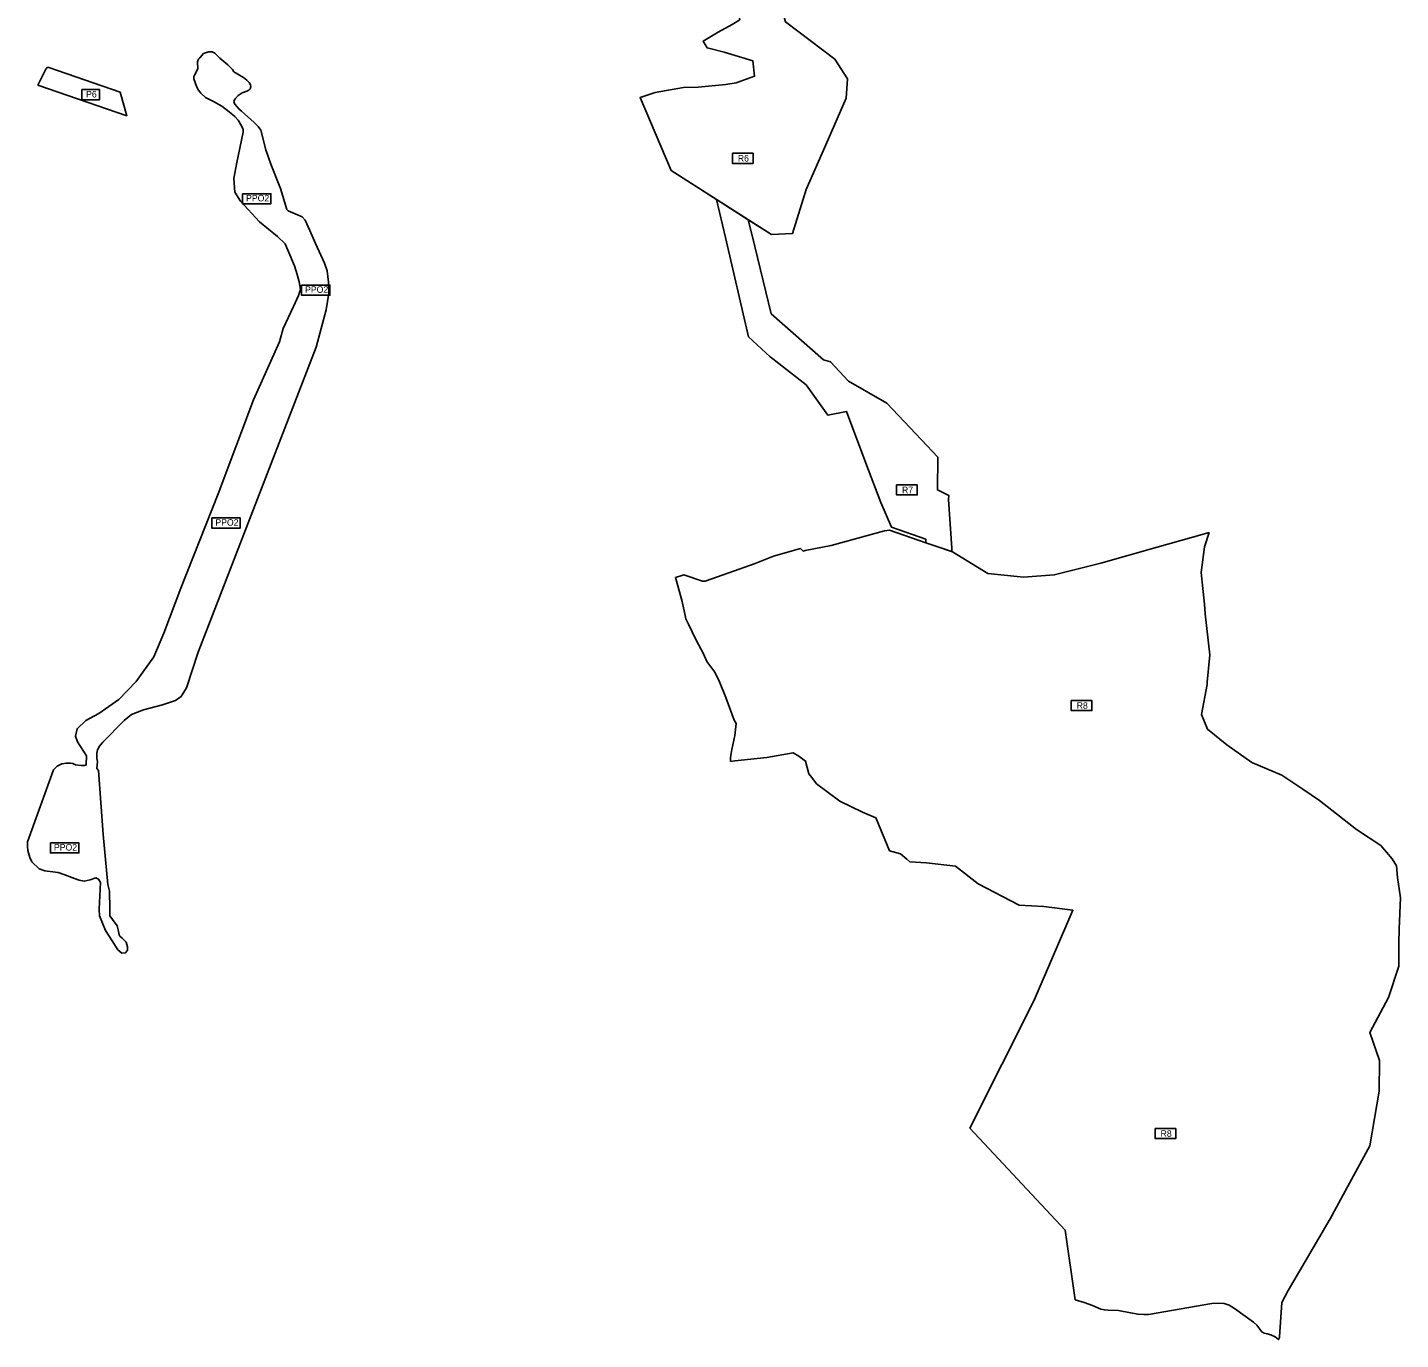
# Model space of a CAD drawing. Extents: x -545342 to -528609, y -1041871 to -1035695.
# Drawn here: x -542551 to -540434, y -1041871 to -1039848 of the extents above; entities that cross this region are included whole.
import ezdxf

# ---------------------------------------------------------------- set-up
doc = ezdxf.new("R2010")
doc.units = 0
for name, color, linetype in [('Vrstva 30', 7, 'Continuous'), ('Vrstva 31', 7, 'Continuous'), ('Vrstva 32', 7, 'Continuous'), ('Vrstva 44', 7, 'Continuous'), ('Vrstva 5', 7, 'Continuous'), ('Vrstva 6', 7, 'Continuous'), ('Vrstva 61', 7, 'Continuous'), ('Vrstva 7', 7, 'Continuous'), ('Vrstva66', 7, 'Continuous')]:
    doc.layers.add(name, color=color, linetype=linetype)

msp = doc.modelspace()

# ---------------------------------------------------------------- linework, layer by layer
at = {"layer": 'Vrstva 30'}
msp.add_lwpolyline([(-540634.1, -1041863.7), (-540627.2, -1041866.5), (-540622.1, -1041870.9), (-540620.8, -1041867.7), (-540620.7, -1041866.5), (-540617.2, -1041813.7), (-540607.4, -1041795), (-540542.4, -1041684.7), (-540512.7, -1041629.5), (-540481.6, -1041572), (-540466.9, -1041488.1), (-540466.7, -1041440.7), (-540481.4, -1041397.5), (-540452.8, -1041343.7), (-540436.6, -1041295), (-540436.6, -1041255.9), (-540436.2, -1041241), (-540436.2, -1041237.7), (-540434.1, -1041189.6), (-540438.6, -1041158.6), (-540440.3, -1041140.5), (-540446.9, -1041129.5), (-540464.2, -1041109.2), (-540501.8, -1041084.2), (-540558.9, -1041039.9), (-540584.7, -1041022.3), (-540617.3, -1041000.7), (-540663.1, -1040981.3), (-540701.9, -1040954.1), (-540731.5, -1040929.6), (-540740.7, -1040906.9), (-540732.4, -1040860.8), (-540732, -1040857.1), (-540728.2, -1040815.2), (-540735.1, -1040752.1), (-540736.5, -1040737.2), (-540738.7, -1040712.9), (-540741.2, -1040688.2), (-540736.1, -1040648.6), (-540729.2, -1040626.7), (-540756.3, -1040634.3), (-540809, -1040649), (-540896, -1040674), (-540968, -1040692), (-541015.2, -1040695.2), (-541025.2, -1040694.1), (-541070.4, -1040689.6), (-541125, -1040656.3), (-541152, -1040647), (-541166, -1040642.2), (-541222, -1040623), (-541229.8, -1040623.8), (-541312, -1040646.4), (-541352.1, -1040654.3), (-541355.1, -1040655.1), (-541357, -1040653.3), (-541359.2, -1040651.3), (-541400.9, -1040663.2), (-541428.9, -1040674.3), (-541460.7, -1040685.5), (-541506, -1040701.4), (-541510.3, -1040701.4), (-541539, -1040692), (-541541.8, -1040692.8), (-541551.9, -1040695.7), (-541550.8, -1040699.6), (-541541.4, -1040733.1), (-541536.3, -1040757), (-541535.7, -1040759.7), (-541531.8, -1040767.9), (-541520.5, -1040791.5), (-541508.8, -1040813.8), (-541503.5, -1040825.3), (-541491.3, -1040841.6), (-541484.1, -1040856.7), (-541474.3, -1040881.1), (-541461.4, -1040915.8), (-541458.3, -1040921.1), (-541460.1, -1040939.4), (-541464.7, -1040961.2), (-541467.2, -1040973.5), (-541466.9, -1040979.4), (-541460.4, -1040978.7), (-541410.9, -1040973.2), (-541370.6, -1040966), (-541361.4, -1040971.4), (-541351.5, -1040979), (-541346.1, -1040998.5), (-541341.8, -1041004.2), (-541334.5, -1041013.9), (-541298.2, -1041041), (-541263.5, -1041057.7), (-541242.7, -1041066.5), (-541242.4, -1041067.3), (-541221.8, -1041117.1), (-541205, -1041121.8), (-541195.2, -1041130), (-541190.3, -1041134.1), (-541165, -1041136), (-541120, -1041141), (-541085, -1041168), (-541022, -1041201), (-540984, -1041203), (-540939, -1041209), (-540998.8, -1041347.7), (-541098, -1041545), (-540951, -1041702), (-540935.4, -1041809.6), (-540921.7, -1041813.6), (-540908.7, -1041818.2), (-540896.1, -1041823.8), (-540890.6, -1041825.1), (-540885, -1041825.8), (-540868.7, -1041826.3), (-540850.1, -1041829.5), (-540838.7, -1041831.8), (-540829.9, -1041832.5), (-540822.6, -1041832), (-540724.9, -1041815.4), (-540715, -1041814.9), (-540706.1, -1041815.4), (-540698.1, -1041817.9), (-540689.8, -1041823), (-540660.5, -1041843.9), (-540655.6, -1041848.6), (-540647.9, -1041859.1), (-540644.4, -1041861.2), (-540639.6, -1041862.3), (-540634.1, -1041863.7)], dxfattribs=at)
at = {"layer": 'Vrstva 31'}
msp.add_lwpolyline([(-541165.9, -1040636.8), (-541218.6, -1040618.3), (-541235.1, -1040580.1), (-541258.1, -1040519.5), (-541288.2, -1040439.9), (-541316.9, -1040445.7), (-541350.1, -1040399), (-541401.9, -1040358.6), (-541405.8, -1040355.7), (-541439.2, -1040324.8), (-541474.8, -1040171.6), (-541488.5, -1040112.9), (-541439.6, -1040144.2), (-541433.7, -1040168.3), (-541404.5, -1040289.1), (-541323.6, -1040360), (-541312.7, -1040363.1), (-541285.3, -1040393), (-541225.8, -1040427.1), (-541172.5, -1040483.8), (-541147.5, -1040510.4), (-541148, -1040560.7), (-541130.4, -1040569.3), (-541131, -1040575.4), (-541125.9, -1040650.7), (-541125.7, -1040656), (-541152, -1040647), (-541165.7, -1040642.3), (-541165.9, -1040636.8)], dxfattribs=at)
at = {"layer": 'Vrstva 32'}
for points in [[(-541306.1, -1039896.5), (-541382.4, -1039839.1), (-541393.7, -1039799.2), (-541405.3, -1039790.4), (-541448.3, -1039803.6), (-541454.8, -1039808.4), (-541460.3, -1039818.1), (-541454.1, -1039827.2), (-541452.7, -1039835.8), (-541464.4, -1039843.4), (-541485.8, -1039854.9), (-541509, -1039868.7), (-541503, -1039879.2), (-541476.8, -1039885.6), (-541432.3, -1039899.4)], [(-541432.3, -1039899.4), (-541429.9, -1039923.1)], [(-541403.8, -1040167), (-541371.5, -1040165.6), (-541350.4, -1040097.4), (-541319.8, -1040028.8), (-541288.9, -1039956.9), (-541286.8, -1039926.8), (-541306.1, -1039896.5)], [(-541429.9, -1039923.1), (-541458.2, -1039933.1), (-541474.1, -1039935.7), (-541517, -1039939.8), (-541539.3, -1039940.2), (-541583.1, -1039948.1), (-541606.4, -1039955.7), (-541558.2, -1040068.4), (-541403.8, -1040167)]]:
    msp.add_lwpolyline(points, dxfattribs=at)
at = {"layer": 'Vrstva 44'}
msp.add_lwpolyline([(-542520.1, -1039908.8), (-542522.2, -1039912.1), (-542534.6, -1039936.6), (-542397.8, -1039983.8), (-542408.1, -1039947.7), (-542517.8, -1039909.6), (-542520.1, -1039908.8)], dxfattribs=at)
at = {"layer": 'Vrstva 5'}
for points in [[(-541210.9, -1040553.1), (-541179.2, -1040553.1), (-541179.2, -1040568.6), (-541210.9, -1040568.6)], [(-540941.6, -1040885.6), (-540909.9, -1040885.6), (-540909.9, -1040901.1), (-540941.6, -1040901.1)], [(-540812.3, -1041545.6), (-540780.6, -1041545.6), (-540780.6, -1041561.1), (-540812.3, -1041561.1)]]:
    msp.add_lwpolyline(points, close=True, dxfattribs=at)
at = {"layer": 'Vrstva 6'}
msp.add_lwpolyline([(-541463.9, -1040041.7), (-541432.2, -1040041.7), (-541432.2, -1040057.3), (-541463.9, -1040057.3)], close=True, dxfattribs=at)
at = {"layer": 'Vrstva 61'}
msp.add_lwpolyline([(-542285.2, -1039894.7), (-542279.3, -1039888), (-542271.9, -1039885.1), (-542266, -1039885.4), (-542262.1, -1039887.2), (-542254.3, -1039894.9), (-542241.7, -1039905.2), (-542234.8, -1039912.7), (-542232.7, -1039916.1), (-542217.8, -1039925.1), (-542212.4, -1039929.2), (-542209, -1039932.5), (-542206.8, -1039936.2), (-542206.6, -1039939), (-542207.6, -1039942.3), (-542209.5, -1039944.5), (-542212.4, -1039946.2), (-542219.9, -1039948.5), (-542225.7, -1039952.5), (-542230.6, -1039957.8), (-542232.1, -1039960.4), (-542232.4, -1039962), (-542232.2, -1039963.4), (-542231.3, -1039966), (-542227.6, -1039970.2), (-542225.1, -1039973.3), (-542221, -1039976.6), (-542216, -1039981), (-542201.1, -1039994.1), (-542195, -1040000.4), (-542190.8, -1040006), (-542183.1, -1040036.5), (-542175.4, -1040058.8), (-542160.9, -1040096), (-542150.8, -1040128.3), (-542148.9, -1040130.6), (-542145.3, -1040132.3), (-542127.5, -1040139.7), (-542122.9, -1040144.9), (-542115.4, -1040160.7), (-542106.6, -1040180.8), (-542092.6, -1040211.4), (-542088.9, -1040223), (-542086.7, -1040240.6), (-542086.2, -1040257.3), (-542090.4, -1040283), (-542105.9, -1040340.8), (-542265.4, -1040753.7), (-542287.4, -1040810.8), (-542305.6, -1040866.1), (-542314, -1040879.6), (-542322.8, -1040885.7), (-542342.8, -1040892.2), (-542371.9, -1040900.1), (-542390.3, -1040907.3), (-542401.8, -1040916.4), (-542434.5, -1040949.7), (-542439.5, -1040955.9), (-542443, -1040961.5), (-542443.8, -1040966.8), (-542443.9, -1040970.1), (-542443.6, -1040974.8), (-542443, -1040979.8), (-542443.7, -1040990.3), (-542441.5, -1040993.5), (-542433.9, -1041092.2), (-542426.9, -1041169.3), (-542424.5, -1041179.5), (-542424, -1041206.9), (-542423.6, -1041217.3), (-542419.6, -1041223.2), (-542412.4, -1041232.8), (-542410.7, -1041239.1), (-542409.5, -1041246.9), (-542408.6, -1041248.9), (-542404.9, -1041251.8), (-542398.8, -1041257.9), (-542396.6, -1041265.1), (-542396.4, -1041270.4), (-542399.6, -1041274.4), (-542405.1, -1041275.2), (-542411.5, -1041269.9), (-542420.3, -1041256.3), (-542430.6, -1041240.1), (-542439.5, -1041217.7), (-542440.3, -1041207.4), (-542438.1, -1041166.4), (-542441, -1041161.1), (-542445.2, -1041158.7), (-542454, -1041161.8), (-542463.3, -1041164.2), (-542470.8, -1041162.6), (-542478.5, -1041160.2), (-542493.4, -1041154.4), (-542503.2, -1041150.9), (-542511.7, -1041149.9), (-542524.2, -1041148.3), (-542532.7, -1041145.3), (-542544.1, -1041134.4), (-542547, -1041127.5), (-542550, -1041116.9), (-542550.5, -1041110.5), (-542550.8, -1041103.6), (-542510.4, -1040992.3), (-542504.9, -1040986.7), (-542497.9, -1040983.1), (-542490.9, -1040982.2), (-542484.7, -1040981.9), (-542480.6, -1040982.9), (-542476.8, -1040984.7), (-542468.1, -1040985.8), (-542462.6, -1040985.7), (-542460.1, -1040984.9), (-542459.9, -1040970.7), (-542473.4, -1040949.2), (-542476.6, -1040940.4), (-542474.3, -1040929.2), (-542460.8, -1040916.2), (-542440.8, -1040905.5), (-542410.1, -1040884.1), (-542383.2, -1040856.1), (-542355.7, -1040818), (-542340.4, -1040781.6), (-542314.4, -1040712.3), (-542256.6, -1040567.1), (-542202.5, -1040421.7), (-542162.1, -1040332.6), (-542156.5, -1040311.7), (-542140.4, -1040277.8), (-542132.7, -1040260.8), (-542130.1, -1040251.7), (-542131.7, -1040239.9), (-542135.2, -1040228.7), (-542139.3, -1040215.5), (-542149.2, -1040191), (-542153.7, -1040181.4), (-542165.4, -1040170.2), (-542193.3, -1040147.4), (-542222.6, -1040115.7), (-542231.1, -1040101.8), (-542232.7, -1040080.6), (-542227.8, -1040056.2), (-542218, -1040009.3), (-542218.1, -1040005.3), (-542220.7, -1039999.3), (-542226, -1039990.7), (-542231, -1039984.9), (-542239.6, -1039977.6), (-542250.9, -1039969.1), (-542263.8, -1039961.8), (-542276.5, -1039955.6), (-542283.6, -1039949.1), (-542287.2, -1039944.2), (-542289.8, -1039940), (-542294.4, -1039926.8), (-542294.1, -1039923.5), (-542293.5, -1039921.2), (-542288.1, -1039911.7), (-542288.4, -1039900.6), (-542286.9, -1039896.5)], close=True, dxfattribs=at)
at = {"layer": 'Vrstva 7'}
for points in [[(-542467.1, -1039943.6), (-542439.7, -1039943.6), (-542439.7, -1039959.2), (-542467.1, -1039959.2)], [(-542219.3, -1040104.1), (-542175.4, -1040104.1), (-542175.4, -1040119.6), (-542219.3, -1040119.6)], [(-542128.2, -1040245.1), (-542084.4, -1040245.1), (-542084.4, -1040260.6), (-542128.2, -1040260.6)], [(-542266.6, -1040604.1), (-542222.7, -1040604.1), (-542222.7, -1040619.7), (-542266.6, -1040619.7)], [(-542515.3, -1041105.1), (-542471.5, -1041105.1), (-542471.5, -1041120.6), (-542515.3, -1041120.6)]]:
    msp.add_lwpolyline(points, close=True, dxfattribs=at)
at = {"layer": 'Vrstva66'}
for points in [[(-541464.4, -1039843.4), (-541485.8, -1039854.9), (-541509, -1039868.7), (-541503, -1039879.2), (-541476.8, -1039885.6), (-541432.3, -1039899.4), (-541429.9, -1039923.1), (-541458.2, -1039933.1), (-541474.1, -1039935.7), (-541517, -1039939.8), (-541539.3, -1039940.2), (-541583.1, -1039948.1), (-541606.4, -1039955.7), (-541558.2, -1040068.4), (-541488.5, -1040112.9), (-541439.6, -1040144.2), (-541403.8, -1040167), (-541371.5, -1040165.6), (-541350.4, -1040097.4), (-541319.8, -1040028.8), (-541288.9, -1039956.9), (-541286.8, -1039926.8), (-541306.1, -1039896.5), (-541382.4, -1039839.1)], [(-541165.7, -1040642.3), (-541152, -1040647), (-541125.7, -1040656), (-541125.9, -1040650.7), (-541131, -1040575.4), (-541130.4, -1040569.3), (-541148, -1040560.7), (-541147.5, -1040510.4), (-541172.5, -1040483.8), (-541225.8, -1040427.1), (-541285.3, -1040393), (-541312.7, -1040363.1), (-541323.6, -1040360), (-541404.5, -1040289.1), (-541433.7, -1040168.3), (-541439.6, -1040144.2), (-541488.5, -1040112.9), (-541474.8, -1040171.6), (-541439.2, -1040324.8), (-541405.8, -1040355.7), (-541401.9, -1040358.6), (-541350.1, -1040399), (-541316.9, -1040445.7), (-541288.2, -1040439.9), (-541258.1, -1040519.5), (-541235.1, -1040580.1), (-541218.6, -1040618.3), (-541165.9, -1040636.8), (-541165.7, -1040642.3)], [(-541165.7, -1040642.3), (-541166, -1040642.2), (-541222, -1040623), (-541229.8, -1040623.8), (-541312, -1040646.4), (-541352.1, -1040654.3), (-541355.1, -1040655.1), (-541357, -1040653.3), (-541359.2, -1040651.3), (-541400.9, -1040663.2), (-541428.9, -1040674.3), (-541460.7, -1040685.5), (-541506, -1040701.4), (-541510.3, -1040701.4), (-541539, -1040692), (-541541.8, -1040692.8), (-541551.9, -1040695.7), (-541550.8, -1040699.6), (-541541.4, -1040733.1), (-541536.3, -1040757), (-541535.7, -1040759.7), (-541531.8, -1040767.9), (-541520.5, -1040791.5), (-541508.8, -1040813.8), (-541503.5, -1040825.3), (-541491.3, -1040841.6), (-541484.1, -1040856.7), (-541474.3, -1040881.1), (-541461.4, -1040915.8), (-541458.3, -1040921.1), (-541460.1, -1040939.4), (-541464.7, -1040961.2), (-541467.2, -1040973.5), (-541466.9, -1040979.4), (-541460.4, -1040978.7), (-541410.9, -1040973.2), (-541370.6, -1040966), (-541361.4, -1040971.4), (-541351.5, -1040979), (-541346.1, -1040998.5), (-541341.8, -1041004.2), (-541334.5, -1041013.9), (-541298.2, -1041041), (-541263.5, -1041057.7), (-541242.7, -1041066.5), (-541242.4, -1041067.3), (-541221.8, -1041117.1), (-541205, -1041121.8), (-541195.2, -1041130), (-541190.3, -1041134.1), (-541165, -1041136), (-541120, -1041141), (-541085, -1041168), (-541022, -1041201), (-540984, -1041203), (-540939, -1041209), (-540998.8, -1041347.7), (-541098, -1041545), (-540951, -1041702), (-540935.4, -1041809.6), (-540921.7, -1041813.6), (-540908.7, -1041818.2), (-540896.1, -1041823.8), (-540890.6, -1041825.1), (-540885, -1041825.8), (-540868.7, -1041826.3), (-540850.1, -1041829.5), (-540838.7, -1041831.8), (-540829.9, -1041832.5), (-540822.6, -1041832), (-540724.9, -1041815.4), (-540715, -1041814.9), (-540706.1, -1041815.4), (-540698.1, -1041817.9), (-540689.8, -1041823), (-540660.5, -1041843.9), (-540655.6, -1041848.6), (-540647.9, -1041859.1), (-540644.4, -1041861.2), (-540639.6, -1041862.3), (-540634.1, -1041863.7), (-540627.2, -1041866.5), (-540622.1, -1041870.9), (-540620.8, -1041867.7), (-540620.7, -1041866.5), (-540617.2, -1041813.7), (-540607.4, -1041795), (-540542.4, -1041684.7), (-540512.7, -1041629.5), (-540481.6, -1041572), (-540466.9, -1041488.1), (-540466.7, -1041440.7), (-540481.4, -1041397.5), (-540452.8, -1041343.7), (-540436.6, -1041295), (-540436.6, -1041255.9), (-540436.2, -1041241), (-540436.2, -1041237.7), (-540434.1, -1041189.6), (-540438.6, -1041158.6), (-540440.3, -1041140.5), (-540446.9, -1041129.5), (-540464.2, -1041109.2), (-540501.8, -1041084.2), (-540558.9, -1041039.9), (-540584.7, -1041022.3), (-540617.3, -1041000.7), (-540663.1, -1040981.3), (-540701.9, -1040954.1), (-540731.5, -1040929.6), (-540740.7, -1040906.9), (-540732.4, -1040860.8), (-540732, -1040857.1), (-540728.2, -1040815.2), (-540735.1, -1040752.1), (-540736.5, -1040737.2), (-540738.7, -1040712.9), (-540741.2, -1040688.2), (-540736.1, -1040648.6), (-540729.2, -1040626.7), (-540756.3, -1040634.3), (-540809, -1040649), (-540896, -1040674), (-540968, -1040692), (-541015.2, -1040695.2), (-541025.2, -1040694.1), (-541070.4, -1040689.6), (-541125, -1040656.3), (-541125.7, -1040656), (-541152, -1040647), (-541165.7, -1040642.3)]]:
    msp.add_lwpolyline(points, dxfattribs=at)

# ---------------------------------------------------------------- texts
at = {"layer": 'Vrstva 5'}
for s, p in [('R7', (-541202.6, -1040565.9)), ('R8', (-540933.3, -1040898.3)), ('R8', (-540803.9, -1041558.3))]:
    msp.add_text(s, height=10, dxfattribs=at).set_placement(p)
at = {"layer": 'Vrstva 6'}
msp.add_text('R6', height=10, dxfattribs=at).set_placement((-541455.7, -1040054.5))
at = {"layer": 'Vrstva 7'}
for s, p in [('P6', (-542460.4, -1039955.7)), ('PPO2', (-542213.8, -1040115.9)), ('PPO2', (-542122.8, -1040256.9)), ('PPO2', (-542261.1, -1040616)), ('PPO2', (-542509.9, -1041116.9))]:
    msp.add_text(s, height=10, dxfattribs=at).set_placement(p)

doc.saveas('drawing.dxf')
